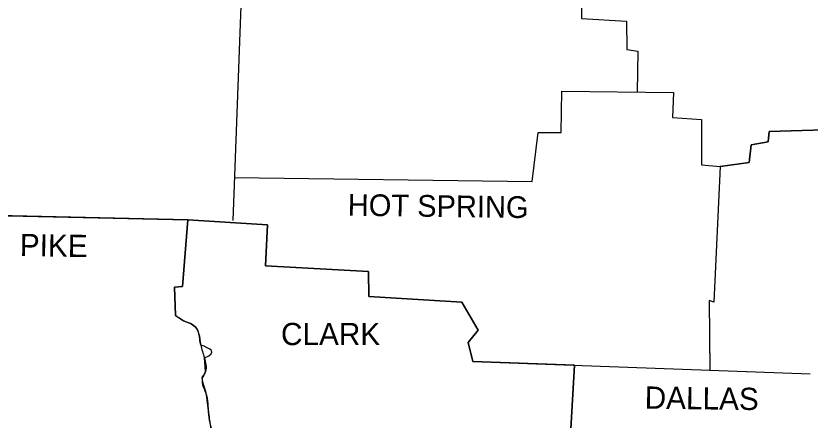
# Model space of a CAD drawing. Extents: x -12863 to 18921, y -8840 to 11152.
# Drawn here: x 11783 to 13285, y 6683 to 7447 of the extents above; entities that cross this region are included whole.
import ezdxf

# ---------------------------------------------------------------- set-up
doc = ezdxf.new("R2010")
doc.units = 0
for name, color, linetype in [('Level 1', 7, 'Continuous'), ('Level 2', 7, 'Continuous'), ('Level 48', 7, 'Continuous')]:
    doc.layers.add(name, color=color, linetype=linetype)

msp = doc.modelspace()

# ---------------------------------------------------------------- linework, layer by layer
at = {"layer": 'Level 1'}
for points in [[(12593.638354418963, 7710.504222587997), (12739.383674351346, 7699.663661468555), (12743.297301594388, 7576.384402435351), (12726.664385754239, 7570.5139616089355), (12724.707572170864, 7504.960704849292), (12852.878865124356, 7496.155043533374), (12852.878865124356, 7442.34266857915), (12938.000258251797, 7437.45063442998), (12938.978665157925, 7383.638259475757), (12959.525208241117, 7380.703038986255), (12958.480338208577, 7303.382645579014)], [(12215.936027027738, 7670.3114568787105), (12193.432670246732, 7060.764009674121)], [(12196.43269704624, 7142.025605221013), (12759.930217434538, 7134.144520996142), (12770.692692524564, 7227.093168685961), (12814.720999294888, 7227.093168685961), (12815.699406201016, 7305.365714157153), (13027.035278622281, 7302.430493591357), (13025.078465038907, 7255.466966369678), (13079.869246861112, 7251.5533390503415), (13079.869246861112, 7165.45353916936), (13115.09189216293, 7162.518318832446)], [(13115.09189216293, 7162.518318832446), (13169.882673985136, 7170.345573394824), (13173.796301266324, 7203.611405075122), (13206.083726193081, 7209.481845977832), (13208.040539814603, 7229.049982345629), (13436.0093283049, 7235.898830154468), (13444.81498958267, 7295.581646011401), (13678.654218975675, 7291.668018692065)], [(13115.09189216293, 7162.518318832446), (13103.35101035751, 6906.175732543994), (13094.545349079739, 6909.11095310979), (13095.523755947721, 6776.047625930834)], [(11541.726566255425, 7074.515305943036), (12108.311277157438, 7061.742416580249)], [(12084.829513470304, 6880.7371554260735), (12082.87269988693, 6934.549530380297), (12098.527208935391, 6935.527937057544), (12108.311277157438, 7061.742416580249), (12258.985927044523, 7051.958348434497), (12255.072299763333, 6974.664209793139), (12449.775256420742, 6963.901734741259), (12450.75366332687, 6916.938207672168), (12626.866890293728, 6906.175732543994), (12657.1975017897, 6853.341764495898), (12638.607772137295, 6829.860000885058), (12647.413433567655, 6793.658948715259), (13285.334678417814, 6770.177185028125)], [(12839.852730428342, 6786.575293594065), (12824.505067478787, 6523.618667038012), (12756.994997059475, 6515.791412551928)]]:
    msp.add_lwpolyline(points, dxfattribs=at)
msp.add_spline([(12084.829513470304, 6880.7371554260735), (12100.48402259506, 6870.953087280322), (12119.073752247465, 6862.147425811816), (12128.857820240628, 6847.471323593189), (12132.771447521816, 6824.967966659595), (12139.620295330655, 6800.507796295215), (12141.577108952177, 6775.069219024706), (12135.706668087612, 6761.371523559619), (12143.533922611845, 6730.062505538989), (12146.469142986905, 6708.537555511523), (12149.404363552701, 6683.098978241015), (12157.231618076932, 6648.854739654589), (12169.950906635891, 6625.37297604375), (12181.691788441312, 6596.9991783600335), (12201.25992480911, 6566.668566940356), (12217.892840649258, 6533.402735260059), (12225.720095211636, 6515.791412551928), (12240.396197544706, 6479.590360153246), (12258.985927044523, 6455.130189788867), (12288.33813159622, 6417.950730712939), (12314.755115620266, 6379.792864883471), (12329.431217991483, 6351.419067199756), (12351.934574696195, 6320.110048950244), (12377.37315200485, 6304.455539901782), (12409.660576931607, 6287.82262409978), (12430.207120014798, 6278.038555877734), (12453.688883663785, 6261.405640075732), (12484.019494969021, 6259.448826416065), (12506.522851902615, 6259.448826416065), (12527.069394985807, 6250.643164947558), (12536.853463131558, 6233.031842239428), (12554.464785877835, 6221.2909603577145), (12568.162481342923, 6217.377333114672)], degree=3, dxfattribs=at)
at = {"layer": 'Level 48'}
for p, q in [((12108.311277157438, 7061.742416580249), (11541.813729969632, 7074.513340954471)), ((12098.527208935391, 6935.527937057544), (12108.311277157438, 7061.742416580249)), ((12141.59154794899, 6775.509816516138), (12139.620295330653, 6800.507796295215)), ((12141.577108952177, 6775.069219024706), (12141.591547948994, 6775.509816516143)), ((13095.515544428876, 6777.164392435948), (13285.334678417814, 6770.177185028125)), ((12157.231618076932, 6648.854739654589), (12149.430175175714, 6682.890797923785))]:
    msp.add_line(p, q, dxfattribs=at)
for points in [[(13678.654218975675, 7291.668018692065), (13631.689211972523, 7292.454043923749), (13444.81498958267, 7295.581646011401), (13436.0093283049, 7235.898830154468), (13208.040539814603, 7229.049982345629), (13206.083726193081, 7209.481845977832), (13173.796301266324, 7203.611405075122), (13169.882673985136, 7170.345573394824), (13115.09189216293, 7162.518318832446)], [(13115.09189216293, 7162.518318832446), (13103.35101035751, 6906.175732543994), (13094.545349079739, 6909.11095310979), (13095.515544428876, 6777.164392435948)], [(12839.852730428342, 6786.575293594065), (12647.413433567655, 6793.658948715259), (12638.607772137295, 6829.860000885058), (12657.1975017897, 6853.341764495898), (12626.866890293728, 6906.175732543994), (12450.75366332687, 6916.938207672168), (12449.775256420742, 6963.901734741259), (12255.072299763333, 6974.664209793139), (12258.985927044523, 7051.958348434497), (12108.311277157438, 7061.742416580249), (12098.527208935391, 6935.527937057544), (12082.87269988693, 6934.549530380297), (12084.829513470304, 6880.7371554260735)], [(12084.829513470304, 6880.7371554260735), (12082.87269988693, 6934.549530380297), (12098.527208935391, 6935.527937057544)], [(12756.994997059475, 6515.791412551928), (12824.505067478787, 6523.618667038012), (12839.852730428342, 6786.575293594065)]]:
    msp.add_lwpolyline(points, dxfattribs=at)
for points in [[(12084.829513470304, 6880.7371554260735), (12100.48402259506, 6870.953087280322), (12119.073752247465, 6862.147425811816), (12128.857820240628, 6847.471323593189), (12132.771447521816, 6824.967966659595), (12139.620295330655, 6800.507796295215), (12141.577108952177, 6775.069219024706), (12135.706668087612, 6761.371523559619), (12143.533922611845, 6730.062505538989), (12146.469142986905, 6708.537555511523), (12149.404363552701, 6683.098978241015), (12157.231618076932, 6648.854739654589), (12169.950906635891, 6625.37297604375), (12181.691788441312, 6596.9991783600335), (12201.25992480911, 6566.668566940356), (12217.892840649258, 6533.402735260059), (12225.720095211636, 6515.791412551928), (12240.396197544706, 6479.590360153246), (12258.985927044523, 6455.130189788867), (12288.33813159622, 6417.950730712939), (12314.755115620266, 6379.792864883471), (12329.431217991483, 6351.419067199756), (12351.934574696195, 6320.110048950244), (12377.37315200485, 6304.455539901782), (12409.660576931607, 6287.82262409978), (12430.207120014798, 6278.038555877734), (12453.688883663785, 6261.405640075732), (12484.019494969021, 6259.448826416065), (12506.522851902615, 6259.448826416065), (12527.069394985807, 6250.643164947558), (12536.853463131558, 6233.031842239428), (12554.464785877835, 6221.2909603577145), (12568.162481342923, 6217.377333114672)], [(12139.620295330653, 6800.507796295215), (12139.620295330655, 6800.507796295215), (12132.771447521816, 6824.967966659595)]]:
    msp.add_spline(points, degree=3, dxfattribs=at)
for points in [[(12116.822284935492, 6863.541651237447), (12111.485436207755, 6866.531726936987), (12105.607926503, 6867.8562547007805), (12100.48402259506, 6870.953087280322), (12095.22827697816, 6874.129603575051), (12089.951846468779, 6877.292155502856), (12084.829513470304, 6880.7371554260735)], [(12132.771447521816, 6824.967966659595), (12130.969095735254, 6832.330535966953), (12130.803692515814, 6840.031075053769), (12128.857820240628, 6847.471323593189), (12127.355170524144, 6853.216863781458), (12124.126769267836, 6858.68154342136), (12119.073752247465, 6862.147425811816), (12118.33682765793, 6862.652885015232), (12117.585078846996, 6863.114280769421), (12116.822284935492, 6863.541651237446)], [(12143.533922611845, 6730.062505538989), (12142.044396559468, 6740.710681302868), (12137.043367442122, 6751.050293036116), (12135.706668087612, 6761.371523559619), (12135.089414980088, 6766.137600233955), (12141.414278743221, 6770.271360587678), (12141.577108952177, 6775.069219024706)], [(12147.291838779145, 6701.643783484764), (12147.029336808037, 6703.942962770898), (12146.758231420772, 6706.241177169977), (12146.469142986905, 6708.537555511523), (12145.564653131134, 6715.7223843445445), (12144.536590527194, 6722.894732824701), (12143.533922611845, 6730.062505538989)], [(12149.430175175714, 6682.890797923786), (12149.42154419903, 6682.960187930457), (12149.412940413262, 6683.029581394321), (12149.404363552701, 6683.098978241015), (12148.640902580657, 6689.27627162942), (12147.997452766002, 6695.463513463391), (12147.291838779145, 6701.643783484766)]]:
    msp.add_open_spline(points, degree=3, dxfattribs=at)

# ---------------------------------------------------------------- texts
at = {"layer": 'Level 2'}
for s, height, rotation, p in [('HOT SPRING', 41.09308632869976, 359.22157224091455, (12410.638983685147, 7069.569671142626)), ('PIKE', 42.06170907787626, 359.0451583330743, (11790.329061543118, 6993.2539393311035)), ('DALLAS', 42.06170907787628, 359.2461527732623, (12972.244496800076, 6704.623928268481))]:
    msp.add_text(s, height=height, rotation=rotation, dxfattribs=at).set_placement(p)
msp.add_text('CLARK', height=42.07344995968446, dxfattribs=at).set_placement((12284.602296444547, 6824.7289203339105))

doc.saveas('drawing.dxf')
